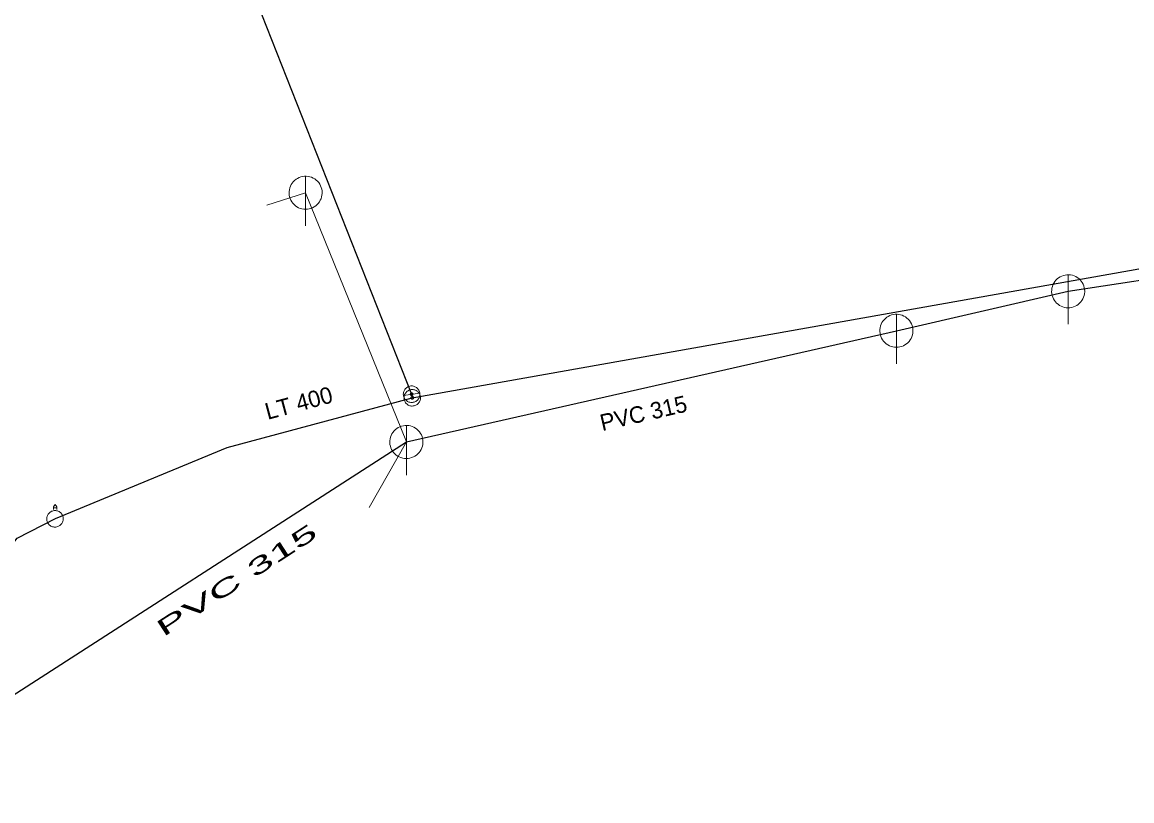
# Model space of a CAD drawing. Extents: x -690535 to -689974, y -975624 to -975325.
# Drawn here: x -690313.5 to -690246.4, y -975474.8 to -975427.6 of the extents above; entities that cross this region are included whole.
import ezdxf

# ---------------------------------------------------------------- set-up
doc = ezdxf.new("R2010")
doc.units = 0
doc.header["$LTSCALE"] = 0.4
for name, color, linetype, lineweight in [('1', 7, 'Continuous', 13), ('11', 7, 'Continuous', 13), ('14', 7, 'Continuous', 25), ('17', 7, 'Continuous', 25), ('22', 7, 'Continuous', 13), ('23', 7, 'Continuous', 13), ('34', 7, 'Continuous', 13), ('47', 7, 'Continuous', 13)]:
    doc.layers.add(name, color=color, linetype=linetype, lineweight=lineweight)

msp = doc.modelspace()

# ---------------------------------------------------------------- linework, layer by layer
at = {"layer": '11'}
for p, q in [((-690298.746, -975438.713), (-690296.394, -975437.959)), ((-690296.394, -975437.959), (-690290.3, -975453.039)), ((-690292.55, -975457), (-690290.3, -975453.039))]:
    msp.add_line(p, q, dxfattribs=at)
at = {"layer": '14', "lineweight": 13}
msp.add_line((-690289.944, -975450.367), (-690289.984, -975450.151), dxfattribs=at)
at = {"layer": '14'}
msp.add_lwpolyline([(-690323.219, -975469.109), (-690315.98, -975469.57), (-690290.3, -975453.039), (-690260.66, -975446.309), (-690250.27, -975443.92), (-690242.07, -975442.67), (-690236.29, -975441.84), (-690209.87, -975436.83), (-690184.76, -975433.33), (-690172.92, -975429.199)], dxfattribs=at)
at = {"layer": '17'}
for points in [[(-690323.245, -975367.198), (-690310.85, -975397.238), (-690289.984, -975450.151)], [(-690289.944, -975450.367), (-690193.294, -975433.208), (-690179.591, -975429.529)], [(-690311.528, -975457.668), (-690301.13, -975453.382), (-690289.944, -975450.367)], [(-690331.378, -975474.754), (-690325.948, -975471.632), (-690321.744, -975465.274), (-690316.903, -975462.792), (-690313.83, -975458.859), (-690311.528, -975457.668)]]:
    msp.add_lwpolyline(points, dxfattribs=at)
at = {"layer": '22'}
for p, q in [((-690296.394, -975439.959), (-690296.393, -975436.959)), ((-690250.27, -975445.92), (-690250.269, -975442.92)), ((-690260.66, -975448.31), (-690260.659, -975445.31)), ((-690290.3, -975455.039), (-690290.299, -975452.039))]:
    msp.add_line(p, q, dxfattribs=at)
for points in [[(-690295.394, -975437.959), (-690295.399, -975437.85), (-690295.417, -975437.742), (-690295.447, -975437.636), (-690295.487, -975437.535), (-690295.539, -975437.438), (-690295.601, -975437.348), (-690295.673, -975437.265), (-690295.753, -975437.191), (-690295.841, -975437.125), (-690295.935, -975437.07), (-690296.035, -975437.025), (-690296.14, -975436.992), (-690296.247, -975436.97), (-690296.356, -975436.96), (-690296.466, -975436.962), (-690296.574, -975436.976), (-690296.681, -975437.001), (-690296.784, -975437.038), (-690296.882, -975437.087), (-690296.974, -975437.145), (-690297.06, -975437.214), (-690297.137, -975437.291), (-690297.206, -975437.377), (-690297.265, -975437.469), (-690297.313, -975437.567), (-690297.35, -975437.67), (-690297.376, -975437.777), (-690297.39, -975437.885), (-690297.393, -975437.995), (-690297.383, -975438.104), (-690297.362, -975438.211), (-690297.328, -975438.315), (-690297.284, -975438.415), (-690297.229, -975438.51), (-690297.163, -975438.598), (-690297.089, -975438.678), (-690297.006, -975438.75), (-690296.916, -975438.812), (-690296.82, -975438.864), (-690296.718, -975438.905), (-690296.613, -975438.935), (-690296.505, -975438.953), (-690296.395, -975438.959), (-690296.286, -975438.953), (-690296.178, -975438.935), (-690296.073, -975438.906), (-690295.971, -975438.865), (-690295.874, -975438.813), (-690295.784, -975438.751), (-690295.701, -975438.68), (-690295.626, -975438.6), (-690295.561, -975438.512), (-690295.505, -975438.418), (-690295.461, -975438.318), (-690295.427, -975438.214), (-690295.405, -975438.106), (-690295.395, -975437.997)], [(-690249.27, -975443.92), (-690249.275, -975443.811), (-690249.293, -975443.703), (-690249.323, -975443.597), (-690249.363, -975443.496), (-690249.415, -975443.399), (-690249.477, -975443.309), (-690249.549, -975443.226), (-690249.629, -975443.152), (-690249.717, -975443.086), (-690249.811, -975443.031), (-690249.911, -975442.986), (-690250.016, -975442.953), (-690250.123, -975442.931), (-690250.232, -975442.921), (-690250.342, -975442.923), (-690250.45, -975442.937), (-690250.557, -975442.962), (-690250.66, -975442.999), (-690250.758, -975443.048), (-690250.85, -975443.106), (-690250.936, -975443.175), (-690251.013, -975443.252), (-690251.082, -975443.338), (-690251.141, -975443.43), (-690251.189, -975443.528), (-690251.226, -975443.631), (-690251.252, -975443.738), (-690251.266, -975443.846), (-690251.269, -975443.956), (-690251.259, -975444.065), (-690251.238, -975444.172), (-690251.204, -975444.276), (-690251.16, -975444.376), (-690251.105, -975444.471), (-690251.039, -975444.559), (-690250.965, -975444.639), (-690250.882, -975444.711), (-690250.792, -975444.773), (-690250.696, -975444.825), (-690250.594, -975444.866), (-690250.489, -975444.896), (-690250.381, -975444.914), (-690250.271, -975444.92), (-690250.162, -975444.914), (-690250.054, -975444.896), (-690249.949, -975444.867), (-690249.847, -975444.826), (-690249.75, -975444.774), (-690249.66, -975444.712), (-690249.577, -975444.641), (-690249.502, -975444.561), (-690249.437, -975444.473), (-690249.381, -975444.379), (-690249.337, -975444.279), (-690249.303, -975444.175), (-690249.281, -975444.067), (-690249.271, -975443.958)], [(-690259.66, -975446.31), (-690259.665, -975446.201), (-690259.683, -975446.093), (-690259.713, -975445.987), (-690259.753, -975445.886), (-690259.805, -975445.789), (-690259.867, -975445.699), (-690259.939, -975445.616), (-690260.019, -975445.542), (-690260.107, -975445.476), (-690260.201, -975445.421), (-690260.301, -975445.376), (-690260.406, -975445.343), (-690260.513, -975445.321), (-690260.622, -975445.311), (-690260.732, -975445.313), (-690260.84, -975445.327), (-690260.947, -975445.352), (-690261.05, -975445.389), (-690261.148, -975445.438), (-690261.24, -975445.496), (-690261.326, -975445.565), (-690261.403, -975445.642), (-690261.472, -975445.728), (-690261.531, -975445.82), (-690261.579, -975445.918), (-690261.616, -975446.021), (-690261.642, -975446.128), (-690261.656, -975446.236), (-690261.659, -975446.346), (-690261.649, -975446.455), (-690261.628, -975446.562), (-690261.594, -975446.666), (-690261.55, -975446.766), (-690261.495, -975446.861), (-690261.429, -975446.949), (-690261.355, -975447.029), (-690261.272, -975447.101), (-690261.182, -975447.163), (-690261.086, -975447.215), (-690260.984, -975447.256), (-690260.879, -975447.286), (-690260.771, -975447.304), (-690260.661, -975447.31), (-690260.552, -975447.304), (-690260.444, -975447.286), (-690260.339, -975447.257), (-690260.237, -975447.216), (-690260.14, -975447.164), (-690260.05, -975447.102), (-690259.967, -975447.031), (-690259.892, -975446.951), (-690259.827, -975446.863), (-690259.771, -975446.769), (-690259.727, -975446.669), (-690259.693, -975446.565), (-690259.671, -975446.457), (-690259.661, -975446.348)], [(-690289.3, -975453.039), (-690289.305, -975452.93), (-690289.323, -975452.822), (-690289.353, -975452.716), (-690289.393, -975452.615), (-690289.445, -975452.518), (-690289.507, -975452.428), (-690289.579, -975452.345), (-690289.659, -975452.271), (-690289.747, -975452.205), (-690289.841, -975452.15), (-690289.941, -975452.105), (-690290.046, -975452.072), (-690290.153, -975452.05), (-690290.262, -975452.04), (-690290.372, -975452.042), (-690290.48, -975452.056), (-690290.587, -975452.081), (-690290.69, -975452.118), (-690290.788, -975452.167), (-690290.88, -975452.225), (-690290.966, -975452.294), (-690291.043, -975452.371), (-690291.112, -975452.457), (-690291.171, -975452.549), (-690291.219, -975452.647), (-690291.256, -975452.75), (-690291.282, -975452.857), (-690291.296, -975452.965), (-690291.299, -975453.075), (-690291.289, -975453.184), (-690291.268, -975453.291), (-690291.234, -975453.395), (-690291.19, -975453.495), (-690291.135, -975453.59), (-690291.069, -975453.678), (-690290.995, -975453.758), (-690290.912, -975453.83), (-690290.822, -975453.892), (-690290.726, -975453.944), (-690290.624, -975453.985), (-690290.519, -975454.015), (-690290.411, -975454.033), (-690290.301, -975454.039), (-690290.192, -975454.033), (-690290.084, -975454.015), (-690289.979, -975453.986), (-690289.877, -975453.945), (-690289.78, -975453.893), (-690289.69, -975453.831), (-690289.607, -975453.76), (-690289.532, -975453.68), (-690289.467, -975453.592), (-690289.411, -975453.498), (-690289.367, -975453.398), (-690289.333, -975453.294), (-690289.311, -975453.186), (-690289.301, -975453.077)]]:
    msp.add_lwpolyline(points, close=True, dxfattribs=at)
at = {"layer": '23'}
msp.add_line((-690311.441, -975457.02), (-690311.637, -975457.02), dxfattribs=at)
for points in [[(-690311.051, -975457.685), (-690311.053, -975457.632), (-690311.062, -975457.58), (-690311.077, -975457.531), (-690311.096, -975457.482), (-690311.12, -975457.436), (-690311.15, -975457.392), (-690311.183, -975457.352), (-690311.22, -975457.316), (-690311.261, -975457.283), (-690311.305, -975457.255), (-690311.352, -975457.231), (-690311.402, -975457.213), (-690311.452, -975457.2), (-690311.503, -975457.193), (-690311.555, -975457.19), (-690311.609, -975457.194), (-690311.659, -975457.202), (-690311.711, -975457.217), (-690311.758, -975457.235), (-690311.805, -975457.259), (-690311.849, -975457.29), (-690311.889, -975457.323), (-690311.926, -975457.361), (-690311.959, -975457.401), (-690311.986, -975457.445), (-690312.009, -975457.493), (-690312.027, -975457.541), (-690312.04, -975457.592), (-690312.047, -975457.644), (-690312.051, -975457.696), (-690312.048, -975457.748), (-690312.039, -975457.8), (-690312.025, -975457.851), (-690312.006, -975457.899), (-690311.981, -975457.944), (-690311.952, -975457.988), (-690311.919, -975458.029), (-690311.881, -975458.066), (-690311.84, -975458.098)], [(-690311.711, -975457.217), (-690311.758, -975457.235), (-690311.805, -975457.259), (-690311.849, -975457.29), (-690311.889, -975457.323), (-690311.926, -975457.361), (-690311.959, -975457.401), (-690311.986, -975457.445), (-690312.009, -975457.493), (-690312.027, -975457.541), (-690312.04, -975457.592), (-690312.047, -975457.644), (-690312.051, -975457.696), (-690312.048, -975457.748), (-690312.039, -975457.8), (-690312.025, -975457.851), (-690312.006, -975457.899), (-690311.981, -975457.944), (-690311.952, -975457.988), (-690311.919, -975458.029), (-690311.881, -975458.066), (-690311.84, -975458.098), (-690311.797, -975458.126), (-690311.749, -975458.149), (-690311.701, -975458.168), (-690311.649, -975458.18), (-690311.598, -975458.187), (-690311.546, -975458.19), (-690311.494, -975458.186), (-690311.442, -975458.178), (-690311.391, -975458.164), (-690311.343, -975458.144), (-690311.296, -975458.12), (-690311.253, -975458.092), (-690311.213, -975458.057), (-690311.176, -975458.021), (-690311.144, -975457.98), (-690311.115, -975457.935), (-690311.092, -975457.888), (-690311.074, -975457.839)], [(-690311.84, -975458.098), (-690311.797, -975458.126), (-690311.749, -975458.149), (-690311.701, -975458.168), (-690311.649, -975458.18), (-690311.598, -975458.187), (-690311.546, -975458.19), (-690311.494, -975458.186), (-690311.442, -975458.178), (-690311.391, -975458.164), (-690311.343, -975458.144), (-690311.296, -975458.12), (-690311.253, -975458.092), (-690311.213, -975458.057), (-690311.176, -975458.021), (-690311.144, -975457.98), (-690311.115, -975457.935), (-690311.092, -975457.888), (-690311.074, -975457.839), (-690311.062, -975457.788), (-690311.054, -975457.737), (-690311.051, -975457.685), (-690311.053, -975457.632), (-690311.062, -975457.58), (-690311.077, -975457.531), (-690311.096, -975457.482), (-690311.12, -975457.436), (-690311.15, -975457.392), (-690311.183, -975457.352), (-690311.22, -975457.316), (-690311.261, -975457.283), (-690311.305, -975457.255), (-690311.352, -975457.231), (-690311.402, -975457.213), (-690311.452, -975457.2), (-690311.503, -975457.193), (-690311.555, -975457.19), (-690311.609, -975457.194), (-690311.659, -975457.202), (-690311.711, -975457.217)], [(-690311.637, -975457.117), (-690311.637, -975456.968), (-690311.538, -975456.817), (-690311.441, -975456.968), (-690311.441, -975457.117)], [(-690311.074, -975457.839), (-690311.062, -975457.788), (-690311.054, -975457.737), (-690311.051, -975457.685)]]:
    msp.add_lwpolyline(points, dxfattribs=at)
at = {"layer": '34'}
msp.add_line((-690290.478, -975450.224), (-690289.489, -975450.078), dxfattribs=at)
at = {"layer": '47'}
for points in [[(-690289.507, -975449.998), (-690289.526, -975449.95), (-690289.549, -975449.903), (-690289.578, -975449.859), (-690289.61, -975449.818), (-690289.647, -975449.781), (-690289.688, -975449.747), (-690289.732, -975449.719), (-690289.778, -975449.695), (-690289.827, -975449.676), (-690289.877, -975449.662), (-690289.929, -975449.653), (-690289.981, -975449.651), (-690290.033, -975449.653), (-690290.085, -975449.661), (-690290.136, -975449.674), (-690290.184, -975449.693), (-690290.231, -975449.716), (-690290.276, -975449.745), (-690290.316, -975449.777), (-690290.353, -975449.814), (-690290.387, -975449.855), (-690290.416, -975449.899), (-690290.44, -975449.946), (-690290.459, -975449.994), (-690290.472, -975450.044), (-690290.481, -975450.096), (-690290.484, -975450.149), (-690290.481, -975450.2), (-690290.473, -975450.252), (-690290.46, -975450.303), (-690290.441, -975450.351), (-690290.418, -975450.398), (-690290.39, -975450.443), (-690290.357, -975450.483), (-690290.32, -975450.52), (-690290.28, -975450.554), (-690290.236, -975450.583), (-690290.189, -975450.607), (-690290.14, -975450.626), (-690290.09, -975450.639), (-690290.038, -975450.648), (-690289.986, -975450.651), (-690289.934, -975450.648), (-690289.882, -975450.64), (-690289.831, -975450.627), (-690289.783, -975450.608), (-690289.736, -975450.585), (-690289.692, -975450.557), (-690289.651, -975450.524), (-690289.614, -975450.487), (-690289.58, -975450.447), (-690289.552, -975450.403), (-690289.528, -975450.357), (-690289.509, -975450.307), (-690289.495, -975450.257), (-690289.486, -975450.205), (-690289.484, -975450.153), (-690289.486, -975450.101), (-690289.494, -975450.049)], [(-690289.447, -975450.309), (-690289.456, -975450.257), (-690289.47, -975450.207), (-690289.49, -975450.159), (-690289.513, -975450.112), (-690289.542, -975450.068), (-690289.576, -975450.028), (-690289.614, -975449.992), (-690289.655, -975449.959), (-690289.698, -975449.931), (-690289.745, -975449.907), (-690289.795, -975449.889), (-690289.846, -975449.877), (-690289.897, -975449.869), (-690289.949, -975449.867), (-690290.001, -975449.87), (-690290.053, -975449.879), (-690290.103, -975449.893), (-690290.152, -975449.913), (-690290.198, -975449.936), (-690290.242, -975449.965), (-690290.282, -975449.999), (-690290.319, -975450.037), (-690290.352, -975450.078), (-690290.38, -975450.121), (-690290.403, -975450.168), (-690290.421, -975450.218), (-690290.434, -975450.269), (-690290.441, -975450.32), (-690290.443, -975450.372), (-690290.44, -975450.424), (-690290.431, -975450.476), (-690290.417, -975450.526), (-690290.398, -975450.576), (-690290.374, -975450.621), (-690290.345, -975450.665), (-690290.312, -975450.705), (-690290.274, -975450.742), (-690290.233, -975450.775), (-690290.189, -975450.803), (-690290.142, -975450.826), (-690290.092, -975450.844), (-690290.042, -975450.857), (-690289.99, -975450.864), (-690289.938, -975450.866), (-690289.886, -975450.863), (-690289.834, -975450.854), (-690289.784, -975450.84), (-690289.735, -975450.821), (-690289.689, -975450.797), (-690289.645, -975450.768), (-690289.605, -975450.735), (-690289.569, -975450.697), (-690289.536, -975450.656), (-690289.508, -975450.612), (-690289.484, -975450.565), (-690289.466, -975450.515), (-690289.454, -975450.465), (-690289.446, -975450.413), (-690289.444, -975450.361)], [(-690289.905, -975450.126), (-690289.908, -975450.117), (-690289.912, -975450.11), (-690289.917, -975450.103), (-690289.922, -975450.096), (-690289.928, -975450.09), (-690289.935, -975450.085), (-690289.942, -975450.08), (-690289.95, -975450.076), (-690289.958, -975450.073), (-690289.966, -975450.07), (-690289.975, -975450.069), (-690289.983, -975450.069), (-690289.992, -975450.069), (-690290, -975450.07), (-690290.008, -975450.072), (-690290.017, -975450.075), (-690290.024, -975450.079), (-690290.031, -975450.084), (-690290.038, -975450.089), (-690290.044, -975450.095), (-690290.049, -975450.102), (-690290.054, -975450.109), (-690290.058, -975450.117), (-690290.062, -975450.125), (-690290.064, -975450.133), (-690290.065, -975450.142), (-690290.065, -975450.15), (-690290.065, -975450.159), (-690290.064, -975450.167), (-690290.062, -975450.175), (-690290.059, -975450.184), (-690290.055, -975450.191), (-690290.05, -975450.198), (-690290.045, -975450.205), (-690290.039, -975450.211), (-690290.033, -975450.217), (-690290.025, -975450.221), (-690290.017, -975450.225), (-690290.009, -975450.229), (-690290.001, -975450.231), (-690289.992, -975450.232), (-690289.984, -975450.232), (-690289.975, -975450.232), (-690289.967, -975450.231), (-690289.959, -975450.229), (-690289.95, -975450.226), (-690289.943, -975450.222), (-690289.936, -975450.217), (-690289.929, -975450.212), (-690289.923, -975450.206), (-690289.917, -975450.2), (-690289.913, -975450.192), (-690289.909, -975450.184), (-690289.906, -975450.176), (-690289.903, -975450.168), (-690289.902, -975450.159), (-690289.902, -975450.151), (-690289.902, -975450.142), (-690289.903, -975450.134)], [(-690289.862, -975450.357), (-690289.863, -975450.348), (-690289.866, -975450.34), (-690289.869, -975450.333), (-690289.873, -975450.325), (-690289.878, -975450.318), (-690289.883, -975450.311), (-690289.889, -975450.305), (-690289.896, -975450.3), (-690289.903, -975450.295), (-690289.911, -975450.291), (-690289.919, -975450.288), (-690289.928, -975450.286), (-690289.936, -975450.285), (-690289.944, -975450.284), (-690289.953, -975450.285), (-690289.962, -975450.286), (-690289.97, -975450.289), (-690289.977, -975450.292), (-690289.985, -975450.296), (-690289.992, -975450.301), (-690289.999, -975450.306), (-690290.005, -975450.312), (-690290.01, -975450.319), (-690290.016, -975450.327), (-690290.019, -975450.334), (-690290.022, -975450.342), (-690290.024, -975450.351), (-690290.025, -975450.359), (-690290.026, -975450.367), (-690290.025, -975450.376), (-690290.024, -975450.385), (-690290.021, -975450.393), (-690290.018, -975450.4), (-690290.014, -975450.408), (-690290.009, -975450.415), (-690290.004, -975450.422), (-690289.998, -975450.428), (-690289.991, -975450.433), (-690289.983, -975450.439), (-690289.976, -975450.442), (-690289.968, -975450.445), (-690289.959, -975450.447), (-690289.951, -975450.448), (-690289.943, -975450.449), (-690289.934, -975450.448), (-690289.925, -975450.447), (-690289.917, -975450.444), (-690289.91, -975450.441), (-690289.902, -975450.437), (-690289.895, -975450.432), (-690289.888, -975450.427), (-690289.882, -975450.421), (-690289.877, -975450.414), (-690289.872, -975450.407), (-690289.868, -975450.399), (-690289.865, -975450.391), (-690289.863, -975450.382), (-690289.862, -975450.374), (-690289.861, -975450.366)]]:
    msp.add_lwpolyline(points, close=True, dxfattribs=at)

# ---------------------------------------------------------------- texts
at = {"layer": '1'}
for s, rotation, p in [('LT 400', 15, (-690298.689, -975451.703)), ('PVC 315 ', 13, (-690278.453, -975452.385))]:
    msp.add_text(s, height=1, rotation=rotation, dxfattribs=at).set_placement(p)
at = {"layer": '1', "width": 2.1}
msp.add_text('PVC 315 ', height=1, rotation=33, dxfattribs=at).set_placement((-690305.008, -975464.867))

doc.saveas('drawing.dxf')
